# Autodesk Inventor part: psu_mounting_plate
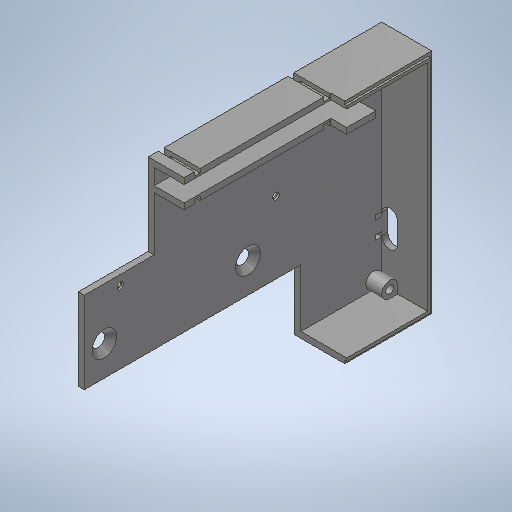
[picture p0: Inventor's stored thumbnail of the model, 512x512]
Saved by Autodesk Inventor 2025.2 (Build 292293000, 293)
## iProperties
Created: 2025-04
Part Number: psu_mounting_plate
Material: 1.0037 S235JR
Document SubType Name: Modeling
Designer: BennF
Density: 7.85 g/cm^3
Appearance: Stahl
Author: BennF
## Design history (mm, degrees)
sketch "Sketch2"
  geometry: L1 (-40.5, 21.5)-(-40.5, -19.5); L2 (-40.5, -19.5)-(68, -19.5); L3 (68, -19.5)-(68, -51.5); L4 (68, -51.5)-(111.5, -51.5); L5 (111.5, -51.5)-(111.5, 62.5); L6 (111.5, 62.5)-(-5.5, 62.5); L7 (-5.5, 62.5)-(-5.5, 21.5); L8 (-5.5, 21.5)-(-40.5, 21.5); L9 (-79.5, 48.5)-(79.5, 48.5); L10 (79.5, 48.5)-(79.5, -48.5); L11 (79.5, -48.5)-(-79.5, -48.5); L12 (-79.5, -48.5)-(-79.5, 48.5); 3 further points
  constraints: 24 end point, 8 perpendicular, 2 midpoint, 2 parallel, 1 horizontal, 1 horizontal alignment, 1 vertical, 1 vertical alignment
  dimensions: "d0" = 159 distance of L9.start L9.end; "d1" = 97 distance of L11.end L9.start; "d2" = 32 distance between parallel lines of L5 L10; "d3" = 14 distance between parallel lines of L9 L6; "d4" = 41 distance of L1.start L1.end; "d5" = 32 distance of L2.end L3.end (computed from d30); "d6" = 120 distance between parallel lines of L1 L10; "d7" = 11.5 distance between parallel lines of L3 L10; "d8" = 85 distance between parallel lines of L7 L10; "d30" = 3 distance between parallel lines of L4 L11
extrude "Extrusion1" new body sketch "Sketch2" distance "d9" = 3; taper "d10" = 0 deg
sketch "Sketch3"
  geometry: L1 (16.5, 55.5)-(16.5, -22.5); L2 (62.5, 111.5)-(62.5, -5.5) reference; L3 (-51.5, 111.5)-(62.5, 111.5) reference; 1 further point
  constraints: 2 end point, 1 vertical, 1 vertical alignment
  dimensions: "d18" = 78 distance of L1.start L1.end; "d19" = 46 distance from line of L1.end L2 (computed from d3); "d27" = 56 distance from line of L3 L1.start (computed from d2)
hole "Hole1" sketch "Sketch3" at (16.5, 55.5), (16.5, -22.5) diameter "d11" = 3.4; stored, may be unused: countersink angle "d15" = 90 deg, drill point angle "d17" = 118 deg; dims "d12" = 6, "d13" = 7.5, "d14" = 2, "d16" = 8
sketch "Sketch4"
  geometry: L1 (4.5, -30.5)-(4.5, 41.5); L2 (-16.5, -22.5)-(-16.5, 55.5); L3 (-21.5, -40.5)-(19.5, -40.5) reference; L4 (51.5, 111.5)-(-62.5, 111.5) reference; C1 r 1.7 at (-16.5, -22.5) reference; C2 r 1.7 at (-16.5, 55.5) reference; 2 further points
  constraints: 4 end point, 2 vertical, 1 midpoint, 1 vertical alignment
  dimensions: "d28" = 21 distance between parallel lines of L1 L2; "d29" = 10 distance from line of L1.start L3; "d72" = 70 distance from line of L1.end L4
hole "Hole2" sketch "Sketch4" at (4.5, -30.5), (4.5, 41.5) diameter "d20" = 5.5; stored, may be unused: countersink angle "d24" = 90 deg, drill point angle "d26" = 118 deg; dims "d21" = 6, "d22" = 12.5, "d23" = 2, "d25" = 8
sketch "Sketch5"
  geometry: L1 (-62.5, 111.5)-(-62.5, -5.5) reference; L2 (51.5, 111.5)-(-62.5, 111.5) reference; L3 (51.5, 68)-(51.5, 111.5) reference; L4 (19.5, 68)-(51.5, 68) reference; L5 (48.5, 68)-(48.5, 108.5); L6 (48.5, 108.5)-(-59.5, 108.5); L7 (-59.5, 108.5)-(-59.5, -5.5); L8 (-62.5, -5.5)-(-21.5, -5.5) reference; L9 (-59.5, 108.5)-(-62.5, 108.5); L10 (-59.5, 108.5)-(-59.5, 111.5); L11 (48.5, 108.5)-(51.5, 108.5); L12 (-51.5, -5.5)-(-51.5, 82.5); L13 (-51.5, 82.5)-(-48.5, 82.5); L14 (-48.5, 82.5)-(-48.5, -5.5); 1 further point
  constraints: 18 end point, 9 perpendicular, 8 point on line, 2 vertical
  dimensions: "d31" = 3 distance of L6.end L10.end (= d30); "d32" = 14 distance between parallel lines of L14 L1 (= d3); "d33" = 88 distance of L13.end L14.end (computed from d8)
extrude "Extrusion2" join sketch "Sketch5" distance "d34" = 15; taper "d35" = 0 deg
workplane "Work Plane1"
sketch "Sketch6"
  geometry: L1 (18, 41)-(18, 38) reference; L2 (18, 30)-(18, 27) reference; L3 (0, 41)-(18, 41) reference; L4 (3, 27)-(18, 27) reference; L5 (0, 41)-(0, 0) reference; L6 (18, 39)-(4, 39); L7 (2, 37)-(2, 31); L8 (4, 29)-(18, 29); L9 (2, 39)-(2, 41); L10 (3, 38)-(3, 30) reference; L11 (2, 39)-(0, 39); L12 (3, 27)-(0, 27); A1 r 2 centre (4, 37) between (4, 39) and (2, 37); A2 r 2 centre (4, 31) between (2, 31) and (4, 29); 3 further points
  constraints: 12 end point, 7 point on line, 5 perpendicular, 4 point on circle, 4 tangent, 2 centre point, 2 horizontal, 2 midpoint, 1 equal radius, 1 horizontal alignment
  dimensions: "d37" = 2 distance of L9.start L9.end; "d38" = 2 radius of A1 (= d37)
extrude "Extrusion3" cut sketch "Sketch6" distance "d39" = 3; taper "d40" = 0 deg
pattern_linear "Rectangular Pattern1" dims "d43" = 65
sketch "Sketch7"
  geometry: L1 (0, 0)-(0, 108) reference; L2 (-3, 31.839)-(0, 31.839); L3 (-3, 20.839)-(0, 20.839); L4 (0, 22.839)-(1, 22.839); L5 (-1, 24.839)-(-1, 27.839); L6 (1, 29.839)-(0, 29.839); L7 (-3, -3)-(-3, 111) reference; L8 (-1, 29.839)-(-1, 31.839); L9 (-1, 22.839)-(-1, 20.839); L10 (-1, 29.839)-(-3, 29.839); L11 (0, 0)-(15, 0) reference; A1 r 2 centre (1, 27.839) between (1, 29.839) and (-1, 27.839); A2 r 2 centre (1, 24.839) between (-1, 24.839) and (1, 22.839); 4 further points
  constraints: 16 end point, 14 point on line, 4 point on circle, 4 tangent, 3 perpendicular, 2 centre point, 2 equal length, 2 horizontal, 1 equal radius, 1 midpoint, 1 parallel, 1 vertical
  dimensions: "d44" = 2 distance between parallel lines of L6 L2; "d45" = 7 distance of L9.start L8.start; "d47" = 2 radius of A1 (derived); "d56" = 26.339 distance from line of L11 point (-1, 26.339)
extrude "Extrusion4" cut sketch "Sketch7" distance "d48" = 3; taper "d49" = 0 deg
sketch "Sketch8"
  geometry: L1 (0, 29.571)-(0, 31.839) reference; L2 (0, 20.839)-(0, 23.107) reference; L3 (4, 31.339)-(4, 21.339); L4 (8, 31.339)-(8, 21.339); L5 (0, 21.339)-(0, 31.339); L6 (0, 29.571)-(0, 23.107); A1 r 4 centre (4, 31.339) between (8, 31.339) and (0, 31.339); A2 r 4 centre (4, 21.339) between (0, 21.339) and (8, 21.339); 7 further points
  constraints: 10 end point, 4 point on circle, 4 tangent, 3 midpoint, 2 centre point, 2 vertical, 1 horizontal alignment, 1 parallel
  dimensions: "d50" = 10 distance of L3.start L3.end; "d51" = 4 radius of A1
extrude "Extrusion5" cut sketch "Sketch8" stored distance "d52" = 3; taper "d53" = 0 deg
sketch "Sketch9"
  geometry: L1 (48.5, 68)-(51.5, 68) reference; L2 (48.5, 108.5)-(48.5, 68) reference; L3 (51.5, 68)-(51.5, 111.5) reference; L4 (-59.5, 108.5)-(48.5, 108.5) reference; L5 (51.5, 111.5)-(-62.5, 111.5) reference; L6 (-62.5, 111.5)-(-62.5, 67.5) reference; L7 (-59.5, -5.5)-(-59.5, 108.5) reference; L8 (-59.5, 68)-(-62.5, 68); L9 (-48.5, 82.5)-(-51.5, 82.5) reference; L10 (-48.5, 67.5)-(-48.5, 82.5) reference; L11 (-51.5, 82.5)-(-48.5, 82.5); L12 (-48.5, 82.5)-(-48.5, 68); L13 (-48.5, 68)-(-51.5, 68); L14 (-51.5, 68)-(-51.5, 82.5); 1 further point
  constraints: 10 end point, 3 point on line, 2 horizontal alignment, 2 parallel, 2 perpendicular, 1 horizontal
extrude "Extrusion6" join sketch "Sketch9" distance "d54" = 7; taper "d55" = 0 deg
sketch "Sketch10"
  geometry: L1 (48.5, 108.5)-(48.5, 68) reference; L2 (-59.5, 68)-(-59.5, 108.5) reference; L3 (-59.5, 108.5)-(48.5, 108.5) reference; A1 r 4 centre (-55.5, 104.5) between (-59.5, 104.5) and (-55.5, 108.5); A2 r 4 centre (44.5, 104.5) between (44.5, 108.5) and (48.5, 104.5); 1 further point
  constraints: 4 point on circle, 4 point on line, 3 tangent, 2 centre point, 1 equal radius, 1 horizontal alignment
  dimensions: "d59" = 8 diameter of A1
extrude "Extrusion7" join sketch "Sketch10" distance "d60" = 8; taper "d61" = 0 deg
sketch "Sketch11"
  geometry: L1 (-59.5, 68)-(-59.5, 108.5) reference; L2 (-59.5, 108.5)-(48.5, 108.5) reference; L3 (48.5, 108.5)-(48.5, 68) reference; L4 (-61, 68)-(-61, 110); L5 (-61, 110)-(50, 110); L6 (50, 110)-(50, 68); L7 (-62.5, 68)-(-59.5, 68) reference; L8 (48.5, 68)-(51.5, 68) reference; L9 (-51.5, 68)-(-48.5, 68) reference; L10 (-48.5, 68)-(-48.5, 82.5) reference; L11 (-48.5, 82.5)-(-51.5, 82.5) reference; L12 (-51.5, 82.5)-(-51.5, 68) reference; 1 further point
  constraints: 6 end point, 2 midpoint, 2 other
  dimensions: "d62" = 1.5 distance between parallel lines of L1 L4
extrude "Extrusion8" join sketch "Sketch11" distance "d63" = 1; taper "d64" = 0 deg
sketch "Sketch12"
  geometry: A1 r 4 centre (55.5, 104.5) between (55.5, 108.5) and (59.5, 104.5) reference; A2 r 4 centre (-44.5, 104.5) between (-48.5, 104.5) and (-44.5, 108.5) reference; 3 further points
  constraints: 2 coincident
hole "Hole3" sketch "Sketch12" at (-44.5, 104.5), (55.5, 104.5) diameter "d65" = 3.2; stored, may be unused: countersink angle "d69" = 90 deg, drill point angle "d71" = 118 deg; dims "d66" = 6, "d67" = 4, "d68" = 6.7, "d70" = 8
body "Solid1"
node "Projected Loop1"
other parameters: "d36" = -5
